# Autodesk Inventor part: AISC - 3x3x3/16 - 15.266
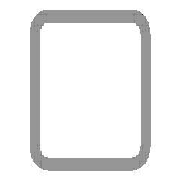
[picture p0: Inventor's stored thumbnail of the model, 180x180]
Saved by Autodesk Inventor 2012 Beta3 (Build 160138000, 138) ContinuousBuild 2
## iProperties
_CCFamilyMember: 9
_CCFamilyDisplayName: ANSI AISC (Square) - Tube
_FrameMemberDoc: Frame Member File
_Version: 15.0.0
_GetPNFromCC: 1
Created: 2011-01
Part Number: AISC - 3x3x3/16 - 15.266
Material: Steel, Mild
Description: Tube
Document SubType Name: Modeling
Standard: ANSI
Designer: Beta-8540w
Standards Organization: ANSI
Language: en-US
Size Designation: 3x3x3/16
Categories: <MemberInstance><Categories><Category DisplayName="Structural Shapes" InternalName="089c4875-fa83-4c05-b084-43b9cc11f5ed" Mnemonic="GRDR"><CategoryParameter Dis
Stock Number: 3x3x3/16
Density: 7.86 g/cm^3
IsCustomPart: 1
G_L: 15.266 in
G_W: 3.000 in
G_H: 3.000 in
+FB874C21-D68D-441B-A299-96FAE1DDA518+CUTDETAIL1: Cut
+EB3DCAF4-50CC-437C-A1F6-2B472C560A7B+CUTDETAIL2: Cut
Author: Beta-8540w
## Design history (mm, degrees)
node "Start plane"
node "End plane"
sketch "Sketch"
  geometry: L1 (-38.1, -28.575)-(-38.1, 28.575); L2 (-28.575, 38.1)-(28.575, 38.1); L3 (38.1, 28.575)-(38.1, -28.575); L4 (28.575, -38.1)-(-28.575, -38.1); L5 (-28.575, 33.337)-(28.575, 33.338); L6 (33.338, 28.575)-(33.338, -28.575); L7 (28.575, -33.337)-(-28.575, -33.338); L8 (-33.338, -28.575)-(-33.338, 28.575); L9 (0, 56.102)-(0, -56.102) reference; L10 (-56.102, 0)-(56.102, 0) reference; A1 r 9.525 centre (-28.575, -28.575) between (-38.1, -28.575) and (-28.575, -38.1); A2 r 9.525 centre (-28.575, 28.575) between (-28.575, 38.1) and (-38.1, 28.575); A3 r 9.525 centre (28.575, 28.575) between (38.1, 28.575) and (28.575, 38.1); A4 r 9.525 centre (28.575, -28.575) between (28.575, -38.1) and (38.1, -28.575); A5 r 4.763 centre (-28.575, 28.575) between (-28.575, 33.337) and (-33.338, 28.575); A6 r 4.763 centre (28.575, 28.575) between (33.338, 28.575) and (28.575, 33.338); A7 r 4.763 centre (28.575, -28.575) between (28.575, -33.337) and (33.338, -28.575); A8 r 4.763 centre (-28.575, -28.575) between (-33.338, -28.575) and (-28.575, -33.338)
  constraints: 16 end point, 16 point on circle, 8 centre point, 8 tangent, 4 parallel, 3 equal radius, 2 perpendicular, 7 other
  dimensions: "d10" = 76.2 distance between parallel lines of L2 L4 (= G_H); "d11" = 76.2 distance between parallel lines of L1 L3 (= G_W); "d12" = 4.7625 distance between parallel lines of L3 L6 (= G_T); "d15" = 38.1 distance between parallel lines of L2 L10 (= 0.5 x d10); "d16" = 38.1 distance between parallel lines of L9 L3 (= 0.5 x d11); "d17" = 9.525 radius of A1 (= G_IR)
extrude "Body" new body sketch "Sketch" stored distance "d3" = 387.75605 (= G_L); taper "d4" = 0 deg
node "Driven Length"
  sketch "Sketch3"
    geometry: L1 (0, 0)-(10, 0) reference
    constraints: 2 end point, 1 horizontal
  workplane "Work Plane3"
  sketch "Sketch4"
    geometry: L1 (-2, 31.109)-(12, 31.109) reference; L2 (-2, 418.865)-(12, 418.865) reference
    dimensions: "d19" = 387.75605 distance between parallel lines of L1 L2 (derived)
workplane "Work Plane4"
split "Split1"
workplane "Work Plane5"
split "Split2"
body "Solid1"
other parameters: "G_W" = 76.2 [user parameter; used in 1 equation term], "G_H" = 76.2 [user parameter; used in 1 equation term], "G_T" = 4.7625 [user parameter; used in 1 equation term], "G_IR" = 9.525 [user parameter; used in 1 equation term], "G_L" = 387.75605 (= d19) [user parameter; used in 1 equation term], "G_OFFSET_START" = -31.10852 [user parameter; used in 1 equation term], "G_OFFSET_END" = -31.10852 [user parameter; used in 1 equation term], "d13" = 31.10852 (= -G_OFFSET_START), "d14" = 418.86457 (= G_OFFSET_END + B_L), "B_L" = 449.97309 [user parameter; used in 1 equation term], "d18" = 90 deg
